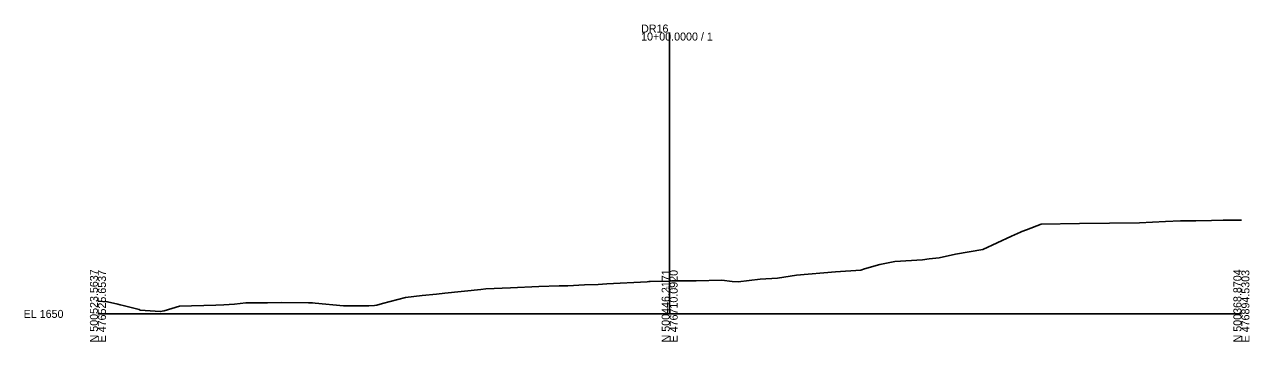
# Model space of a CAD drawing. Extents: x -26 to 403, y -10 to 1535.
# Drawn here: x -25.7 to 402.8, y -9.7 to 101.4 of the extents above; entities that cross this region are included whole.
import ezdxf

# ---------------------------------------------------------------- set-up
doc = ezdxf.new("R2010")
doc.units = 0
for name, color, linetype in [('Exist Cross Section Cell', 7, 'Continuous'), ('Exist XS Center Line Elevation Label', 7, 'Continuous'), ('Exist XS Ground Line', 7, 'Continuous')]:
    doc.layers.add(name, color=color, linetype=linetype)

msp = doc.modelspace()

# ---------------------------------------------------------------- linework, layer by layer
at = {"layer": 'Exist Cross Section Cell'}
for p, q in [((200, 0), (200, 98.59)), ((0, 0), (200, 0)), ((200, 0), (400, 0))]:
    msp.add_line(p, q, dxfattribs=at)
at = {"layer": 'Exist XS Ground Line'}
msp.add_lwpolyline([(0, 4.51), (3.4, 4.18), (6.92, 3.37), (7.83, 3.16), (8.81, 2.99), (14.41, 1.49), (14.75, 1.36), (21.77, 0.78), (23.19, 1.07), (28.49, 2.65), (41.19, 3.03), (44.08, 3.13), (47.81, 3.43), (51.72, 3.9), (53.36, 3.86), (59.36, 3.91), (64.2, 3.99), (73.68, 3.86), (75.05, 3.83), (76.04, 3.76), (85.89, 2.8), (94.72, 2.88), (96.74, 2.94), (97.57, 3.08), (99.54, 3.66), (107.58, 5.72), (113.4, 6.4), (118.43, 6.96), (121.31, 7.21), (133.89, 8.49), (135.75, 8.76), (144.37, 9.09), (154.18, 9.59), (161.33, 9.78), (164.33, 9.88), (170.24, 10.14), (175.03, 10.35), (178.02, 10.57), (192.12, 11.28), (192.74, 11.32), (193.14, 11.36), (200, 11.51), (200.8, 11.53), (201.78, 11.56), (204.44, 11.63), (207.55, 11.53), (209.3, 11.59), (218.22, 11.87), (221.85, 11.37), (223.94, 11.24), (231.63, 12.22), (237.77, 12.57), (244.39, 13.6), (258.02, 14.78), (266.83, 15.29), (268.13, 15.74), (273.48, 17.35), (278.77, 18.36), (288.42, 18.97), (290.82, 19.34), (294.24, 19.67), (300.04, 20.94), (309.56, 22.51), (319.64, 27.18), (322.7, 28.65), (323.22, 28.89), (324.79, 29.4), (329.95, 31.47), (343.41, 31.68), (364.35, 31.96), (373.4, 32.35), (378.73, 32.58), (384.03, 32.64), (389.58, 32.7), (393.58, 32.8), (400, 32.86)], dxfattribs=at)

# ---------------------------------------------------------------- texts
at = {"layer": 'Exist Cross Section Cell'}
for s, p in [('10+00.0000 / 1', (190, 95.79)), ('DR16', (190, 98.59)), ('EL 1650', (-26, -1.4))]:
    msp.add_text(s, height=2.8, dxfattribs=at).set_placement(p)
for s, p in [('N 500523.5637', (0, -10)), ('E 476525.6537', (2.8, -10)), ('N 500446.2171', (200, -10)), ('E 476710.0920', (202.8, -10)), ('N 500368.8704', (400, -10)), ('E 476894.5303', (402.8, -10))]:
    msp.add_text(s, height=2.8, rotation=90, dxfattribs=at).set_placement(p)
at = {"layer": 'Exist XS Center Line Elevation Label'}
msp.add_text('1661.51', height=0.75, dxfattribs=at).set_placement((198.58, 8.76))

doc.saveas('drawing.dxf')
